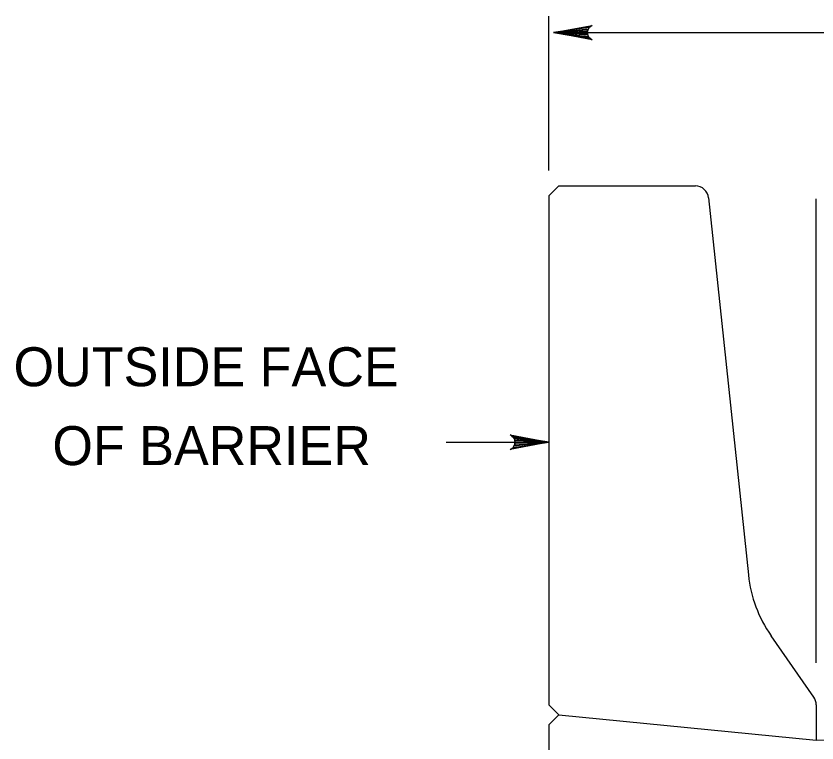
# Model space of a CAD drawing. Extents: x 636530 to 644067, y 294168 to 299122.
# Drawn here: x 639598.3 to 639660, y 296439.5 to 296495.5 of the extents above; entities that cross this region are included whole.
import ezdxf

# ---------------------------------------------------------------- set-up
doc = ezdxf.new("R2010")
doc.units = 0
doc.layers.add('1', color=7, linetype='Continuous')

msp = doc.modelspace()

# ---------------------------------------------------------------- linework, layer by layer
at = {"layer": '1'}
for p, q in [((639639.335, 296483.609), (639639.335, 296495.493)), ((639639.684, 296494.216), (639825.432, 296494.216)), ((639639.335, 296481.646), (639640.097, 296482.408)), ((639640.097, 296482.408), (639650.613, 296482.408)), ((639639.335, 296481.646), (639639.335, 296442.455)), ((639651.623, 296481.498), (639654.685, 296452.461)), ((639659.909, 296445.689), (639659.909, 296481.41)), ((639631.418, 296462.677), (639639.335, 296462.677)), ((639659.726, 296443.045), (639656.43, 296447.778)), ((639659.909, 296439.736), (639757.445, 296443.637)), ((639639.335, 296442.455), (639640.097, 296441.693)), ((639659.909, 296442.465), (639659.909, 296439.736)), ((639639.335, 296440.931), (639640.097, 296441.693)), ((639640.097, 296441.693), (639659.909, 296439.736)), ((639639.335, 296440.931), (639639.335, 296420.61))]:
    msp.add_line(p, q, dxfattribs=at)
for points in [[(639639.684, 296494.216), (639642.666, 296494.775), (639642.551, 296494.695), (639642.437, 296494.616), (639642.377, 296494.516), (639642.318, 296494.416), (639642.301, 296494.316), (639642.284, 296494.216), (639642.301, 296494.116), (639642.318, 296494.016), (639642.377, 296493.916), (639642.437, 296493.816), (639642.551, 296493.736), (639642.666, 296493.656), (639639.684, 296494.216), (639642.551, 296493.736), (639642.437, 296493.816), (639639.684, 296494.216), (639642.377, 296493.916), (639642.318, 296494.016), (639639.684, 296494.216), (639642.301, 296494.116), (639642.284, 296494.216), (639639.684, 296494.216), (639642.301, 296494.316), (639642.318, 296494.416), (639639.684, 296494.216), (639642.377, 296494.516), (639642.437, 296494.616), (639639.684, 296494.216), (639642.551, 296494.695)], [(639639.335, 296462.677), (639636.352, 296462.118), (639636.467, 296462.197), (639636.582, 296462.277), (639636.641, 296462.377), (639636.7, 296462.477), (639636.718, 296462.577), (639636.735, 296462.677), (639636.718, 296462.777), (639636.7, 296462.877), (639636.641, 296462.977), (639636.582, 296463.077), (639636.467, 296463.156), (639636.352, 296463.236), (639639.335, 296462.677), (639636.467, 296463.156), (639636.582, 296463.077), (639639.335, 296462.677), (639636.641, 296462.977), (639636.7, 296462.877), (639639.335, 296462.677), (639636.718, 296462.777), (639636.735, 296462.677), (639639.335, 296462.677), (639636.718, 296462.577), (639636.7, 296462.477), (639639.335, 296462.677), (639636.641, 296462.377), (639636.582, 296462.277), (639639.335, 296462.677), (639636.467, 296462.197)]]:
    msp.add_lwpolyline(points, dxfattribs=at)
for centre, radius, start, end in [((639650.613, 296481.392), 1.016, 6.01952, 90), ((639664.662, 296453.513), 10.033, 186.01952, 214.8593), ((639658.893, 296442.465), 1.016, 0, 34.8593), ((639658.893, 296442.465), 1.016, 0, 34.8593)]:
    msp.add_arc(centre, radius, start, end, dxfattribs=at)

# ---------------------------------------------------------------- texts
for s, p in [('OUTSIDE FACE', (639598.121, 296466.989)), ('OF BARRIER', (639601.109, 296460.917))]:
    msp.add_text(s, height=3, dxfattribs=at).set_placement(p)

doc.saveas('drawing.dxf')
